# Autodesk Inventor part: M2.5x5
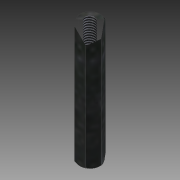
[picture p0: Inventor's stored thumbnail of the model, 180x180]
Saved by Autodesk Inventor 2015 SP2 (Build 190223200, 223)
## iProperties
Created: 2012-08
Part Number: M2.5x5
Material: Stahl
Document SubType Name: Modeling
Designer: rYan
Density: 7.85 g/cm^3
Mass: 3.36246 g
Surface Area: 5.74911 cm^2
Volume: 0.428339 cm^3
Appearance: Platte
Author: rYan
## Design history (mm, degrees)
derived "Abstandsbolzen Typ A.ipt"
feature "Volumenkörper1::Abstandsbolzen Typ A.ipt"
tag "Bezeichnung1"
node "Volumenkörper1"
other parameters: "SW" = 4, "L" = 25, "d2" = 0, "d16" = 45 deg
